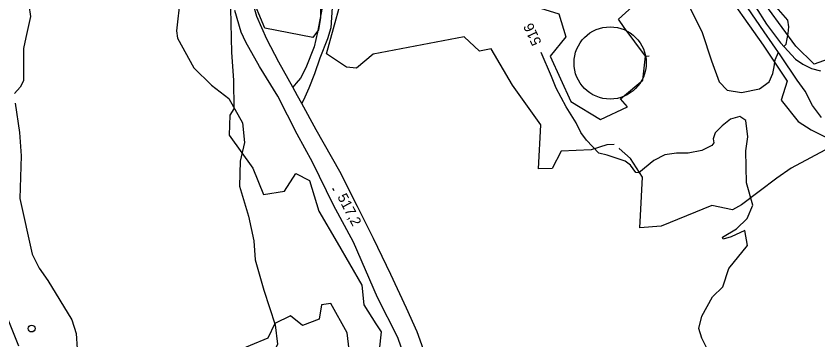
# Model space of a CAD drawing. Extents: x 347312 to 350503, y 6073086 to 6076432.
# Drawn here: x 347759 to 347994.5, y 6075069.6 to 6075164.7 of the extents above; entities that cross this region are included whole.
import ezdxf

# ---------------------------------------------------------------- set-up
doc = ezdxf.new("R2010")
doc.units = 0
for name, color, linetype in [('Level 1', 7, 'Continuous'), ('Level 2', 7, 'Continuous'), ('Level 21', 7, 'Continuous'), ('Level 3', 7, 'Continuous'), ('Level 33', 7, 'Continuous'), ('Level 36', 7, 'Continuous'), ('Level 44', 7, 'Continuous')]:
    doc.layers.add(name, color=color, linetype=linetype)

msp = doc.modelspace()

# ---------------------------------------------------------------- linework, layer by layer
at = {"layer": 'Level 1'}
for points in [[(347757.43, 6075179.1), (347762.11, 6075169.94), (347762.8, 6075167.82), (347763.29, 6075164.48), (347761.89, 6075158.37), (347761.21, 6075155.14), (347761.19, 6075151.91), (347761.26, 6075145.67), (347760.27, 6075143.79), (347758.6, 6075141.89)], [(347758.78, 6075139.09), (347760.02, 6075130.46), (347760.56, 6075123.67), (347760.09, 6075111.11), (347763.76, 6075094.8), (347765.8, 6075090.66), (347768.31, 6075087.06), (347775.43, 6075075.49), (347776.68, 6075071.49), (347777.02, 6075067)]]:
    msp.add_lwpolyline(points, dxfattribs=at)
at = {"layer": 'Level 2'}
for points in [[(347819, 6075203.21), (347813.36, 6075199.84), (347809.35, 6075195.59), (347808.59, 6075189.43), (347810.21, 6075183.09), (347809.93, 6075176.88), (347807.23, 6075169.99), (347806.19, 6075160.3), (347806.48, 6075158.16), (347811.23, 6075149.5), (347816.43, 6075144.34), (347821.53, 6075140.46)], [(347956.34, 6075168.29), (347960.5, 6075159.81), (347963.3, 6075151.51), (347965.55, 6075145.31), (347967.83, 6075142.94), (347972.09, 6075142.23), (347977.37, 6075143.27), (347980.18, 6075145.38), (347981.3, 6075147.82), (347981.67, 6075149.78), (347981.92, 6075151.85), (347982.89, 6075154.06)], [(347985.15, 6075156.42), (347985.8, 6075159.5), (347985.97, 6075161.5), (347985.63, 6075163.47), (347981.54, 6075168.15)], [(347984.5, 6075155.75), (347985.15, 6075156.42)], [(347964.37, 6075130.34), (347963.79, 6075128.66), (347963.99, 6075127.49), (347963.34, 6075126.68), (347960.47, 6075125.21), (347956.36, 6075124.41), (347953.03, 6075124.42), (347953.03, 6075124.42), (347949.51, 6075123.88), (347946.3, 6075122.25), (347941.93, 6075118.6), (347941.08, 6075118.71), (347939.52, 6075120.85), (347937.87, 6075122.02), (347932.61, 6075123.84), (347930.13, 6075124.39), (347926.51, 6075128.19), (347924.92, 6075130.46), (347923.48, 6075133.28), (347920.55, 6075138.01), (347917.61, 6075143.53), (347916.31, 6075146.96), (347913.19, 6075153.94)], [(347821.53, 6075140.46), (347825.53, 6075133.34), (347826.15, 6075127.58), (347824.83, 6075122.07), (347824.66, 6075114.75), (347827.24, 6075105.92), (347828.83, 6075098.73), (347829.21, 6075093.07), (347831.83, 6075084.19), (347835.1, 6075074.08), (347835.76, 6075068.35), (347833.41, 6075063.47), (347831.75, 6075058.65), (347827.99, 6075055.44), (347821.61, 6075050.19), (347813.97, 6075050.84), (347814.06, 6075048.82)], [(347963.67, 6075063.71), (347960.45, 6075070.08), (347959.53, 6075072.98), (347960.39, 6075076.62), (347963.56, 6075082.26), (347966.6, 6075085.17), (347968.32, 6075090.57), (347973.79, 6075097.3), (347973.01, 6075101.74), (347969, 6075099.89), (347966.65, 6075099.21), (347966.45, 6075099.72), (347970.6, 6075102.2), (347973.77, 6075105.22), (347975.44, 6075109.16), (347973.54, 6075115.74), (347973.33, 6075125.07), (347973.91, 6075129.22), (347973.32, 6075133.97), (347971.59, 6075135.14), (347968.84, 6075134.41), (347966.35, 6075132.4), (347964.37, 6075130.34)]]:
    msp.add_lwpolyline(points, dxfattribs=at)
at = {"layer": 'Level 21'}
for points in [[(347815.69, 6075277.67), (347824.05, 6075277.86), (347833.36, 6075279.22), (347836.1, 6075279.62), (347838.04, 6075279.83), (347839.58, 6075270.73), (347841.13, 6075253.27), (347843.63, 6075238.25), (347844.91, 6075225.34), (347845.55, 6075216.23), (347847.18, 6075206.39), (347849.03, 6075197.62), (347849.88, 6075191.76), (347850.67, 6075183.37), (347851.88, 6075174.22), (347851.99, 6075168.7), (347851.43, 6075161.21), (347850.48, 6075157.95), (347848.25, 6075152.28), (347846.7, 6075147.69), (347845.05, 6075143.48), (347843.79, 6075140.86), (347842.94, 6075139.02)], [(347817.44, 6075271.41), (347821.41, 6075272.15), (347832.18, 6075273.67), (347833.56, 6075272.73), (347834.32, 6075271.64), (347835.39, 6075262.75), (347836.42, 6075251.65), (347837.73, 6075242.81), (347838.03, 6075235.29), (347838.59, 6075228.51), (347840.37, 6075220.28), (347842.96, 6075210.64), (347845.02, 6075199.28), (347847.35, 6075191.74), (347847.78, 6075185.22), (347847.75, 6075177.72), (347848.97, 6075172.76), (347848.95, 6075167.14), (347847.56, 6075159.92), (347846.56, 6075155.65), (347844.17, 6075149.46), (347842.55, 6075146.47), (347841.31, 6075144.91), (347840.29, 6075143.82)], [(347879.16, 6075065.4), (347876.82, 6075071.98), (347873.7, 6075078.95), (347869.05, 6075088.84), (347864.01, 6075099.37), (347859.32, 6075108.76), (347854.14, 6075119.02), (347847.17, 6075131.23), (347842.94, 6075139.02), (347841.72, 6075141.26), (347840.29, 6075143.82), (347836.22, 6075151.09), (347832.72, 6075157.88), (347829.74, 6075164.51), (347828.51, 6075168.94)], [(347874.97, 6075059.22), (347871.12, 6075070.29), (347865.21, 6075082.05), (347858.12, 6075098.27), (347852.3, 6075109.2), (347846.07, 6075121.79), (347841.6, 6075130.02), (347835.88, 6075141.18), (347830.56, 6075149.89), (347826.48, 6075157.03), (347825.15, 6075159.88), (347823.29, 6075166.32)], [(347995.6, 6075134.85), (347992.9, 6075138.44), (347990.75, 6075142.64), (347988.43, 6075145.88), (347983.65, 6075152.97), (347978.77, 6075159.98), (347973.79, 6075167.13)], [(347976.22, 6075167.36), (347979.39, 6075162.3), (347983.54, 6075156.78), (347987.97, 6075152.01), (347990.04, 6075150.52), (347992.62, 6075149.22), (347995.26, 6075148.58)]]:
    msp.add_lwpolyline(points, dxfattribs=at)
at = {"layer": 'Level 3'}
msp.add_line((347851.99, 6075114.17), (347852.36, 6075113.46), dxfattribs=at)
at = {"layer": 'Level 33'}
msp.add_circle((347933.48, 6075150.89), 10.6, dxfattribs=at)
at = {"layer": 'Level 36'}
msp.add_circle((347763.6, 6075072.94), 1, dxfattribs=at)
at = {"layer": 'Level 44'}
for points in [[(347846.22, 6075158.39), (347832.13, 6075161.13), (347828.12, 6075170.77), (347825.89, 6075191.01), (347827.46, 6075197.55), (347824.77, 6075205.62), (347824.27, 6075218.05), (347828.67, 6075220.83), (347826.82, 6075227.35), (347823.71, 6075229.83), (347820.98, 6075247.26), (347817.95, 6075268.63), (347819.52, 6075271.59), (347833.37, 6075272.55), (347834.97, 6075269.55), (347837.6, 6075243.82), (347839.13, 6075223.89), (347844.43, 6075200.69), (347846.52, 6075183.31), (347846.4, 6075178.44), (347848.55, 6075170.67), (347848.44, 6075164.16), (347847.8, 6075160.63), (347846.22, 6075158.39)], [(348004.07, 6075154.37), (347993.43, 6075150.58), (347988.04, 6075155.79), (347979.99, 6075166.76), (347966.09, 6075188.75), (347952.38, 6075206.87), (347937.59, 6075223.86), (347929.04, 6075230.74), (347914.25, 6075245.1), (347903.16, 6075256.08), (347891.02, 6075268.36)], [(347943.91, 6075152.92), (347937.64, 6075161.32), (347935.91, 6075163.76), (347944.09, 6075171.19), (347939.6, 6075172.98), (347930.53, 6075172), (347928.08, 6075177.45), (347923.78, 6075183.14), (347915.34, 6075184.63), (347904.54, 6075179.81), (347903.62, 6075176.95), (347909.19, 6075168.12), (347918.41, 6075165.33), (347920.49, 6075158.53), (347915.89, 6075152.9), (347921.95, 6075139.53), (347930.7, 6075134.25), (347938.64, 6075138.04), (347936.56, 6075140.35), (347943.1, 6075145.8), (347943.91, 6075152.92), (347944.92, 6075153)], [(347965.44, 6075174.62), (347978.43, 6075156.15), (347985.5, 6075145.57), (347983.76, 6075139.93), (347988.67, 6075133.69), (347992.53, 6075131.22), (347998.39, 6075128.32)], [(347821.86, 6075171.29), (347822.25, 6075153.98), (347822.89, 6075145.86), (347823.03, 6075137.46), (347821.79, 6075135.53), (347821.59, 6075129.69), (347828.61, 6075120.01), (347831.74, 6075112.32), (347837.85, 6075113.23), (347841.17, 6075118.4), (347845.23, 6075116.4), (347847.99, 6075107.35), (347853.35, 6075098.22), (347860.53, 6075085.67), (347861.15, 6075079.91), (347864.72, 6075074.37), (347866.22, 6075072.03), (347865.65, 6075066.62)], [(347856.07, 6075149.65), (347850.23, 6075153.6), (347854.35, 6075168.39)], [(347934.7, 6075126.97), (347932.48, 6075126.9), (347927.93, 6075125.35), (347919.09, 6075125.01), (347916.42, 6075119.94), (347912.5, 6075119.81), (347913.1, 6075132.73), (347904.86, 6075144.4), (347898.56, 6075155), (347895.08, 6075154.33), (347890.65, 6075158.56), (347863.93, 6075153.46), (347858.99, 6075149.34), (347856.07, 6075149.65)], [(347998.02, 6075126.07), (347986.61, 6075119.99), (347982.43, 6075117.1), (347972.07, 6075109.21), (347969.41, 6075107.74), (347963.33, 6075109.1), (347948.5, 6075103.01), (347942.17, 6075102.52), (347942.42, 6075106.17), (347942.95, 6075117.38), (347939.44, 6075122.83), (347936.11, 6075125.74), (347936.21, 6075125.85)], [(347837.55, 6075059.39), (347845.93, 6075059.2), (347849.06, 6075054.19), (347855.17, 6075055.11), (347857.41, 6075061.75), (347856.27, 6075071.72), (347851.51, 6075080.31), (347848.7, 6075079.91), (347848, 6075075.73), (347843.1, 6075073.89), (347839.61, 6075076.65), (347835.01, 6075074.46), (347832.98, 6075070.08), (347817.42, 6075063.66), (347814.18, 6075060.21), (347813.96, 6075057.79), (347820.59, 6075056.46), (347831.43, 6075057.43), (347837.55, 6075059.39)], [(347759.87, 6075067.81), (347755.77, 6075078.09)]]:
    msp.add_lwpolyline(points, dxfattribs=at)

# ---------------------------------------------------------------- texts
at = {"layer": 'Level 2'}
msp.add_text('516', height=3, rotation=114.9287, dxfattribs=at).set_placement((347913.42, 6075156.85))
at = {"layer": 'Level 3'}
msp.add_text('517,2', height=3, rotation=297.592, dxfattribs=at).set_placement((347853.29, 6075111.61))

doc.saveas('drawing.dxf')
